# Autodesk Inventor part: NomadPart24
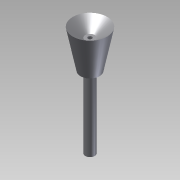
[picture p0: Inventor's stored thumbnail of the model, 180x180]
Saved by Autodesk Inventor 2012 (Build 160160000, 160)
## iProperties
Created: 2012-10
Part Number: NomadPart24
Material: Default
Document SubType Name: Modeling
Designer: TechShop Member
Density: 1 g/cm^3
Author: TechShop Member
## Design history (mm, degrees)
sketch "Sketch1"
  geometry: L1 (6.35, 134.62)-(12.7, 134.62); L2 (22.86, 185.42)-(12.7, 134.62); L3 (0, 172.72)-(6.35, 172.72); L4 (6.35, 172.72)-(22.86, 185.42); L5 (6.35, 134.62)-(6.35, 39.37); L6 (6.35, 39.37)-(0, 39.37); L7 (0, 39.37)-(0, 172.72); 1 further point
  constraints: 14 end point, 2 perpendicular, 1 parallel
  dimensions: "d3" = 6.35 distance of L1.start L1.end; "d7" = 6.35 distance of L3.start L3.end; "d9" = 95.25 distance of L1.start L5.end
revolve "Revolution2" sketch "Sketch1" stored, may be unused: angle "d10" = 90 deg
sketch "Sketch2"
  geometry: C1 r 6.35 at (0, 0) reference; 1 further point
  constraints: 1 coincident
hole "Hole1" sketch "Sketch2" at (0, 0) diameter "d11" = 5.207; stored, may be unused: countersink angle "d15" = 82 deg, drill point angle "d17" = 118 deg; dims "d12" = 19.05, "d13" = 9.525, "d14" = 6.35, "d16" = 25.4
body "Solid2"
